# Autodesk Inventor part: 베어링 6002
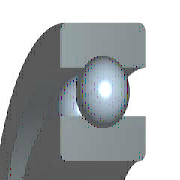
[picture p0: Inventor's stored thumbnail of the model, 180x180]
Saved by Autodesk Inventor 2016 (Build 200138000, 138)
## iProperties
IsCustomPart: 0
Created: 2012-02
Part Number: 베어링 6002
Material: 강철, 연강
Description: 깊은 그루브 볼 베어링
Document SubType Name: Modeling
Standard: KS B 2023
Designer: mduedu
Standards Organization: KS
Language: ko-KR
Size Designation: 6002 - 15 x 32 x 9
Categories: <MemberInstance><Categories><Category DisplayName="샤프트 부품" InternalName="7f7aeb1f-a693-4053-b835-cee3144e0d98" Mnemonic="SHFT"><Category DisplayName="베어링" Inter
Density: 1 g/cm^3
Appearance: 노란색
Author: mduedu
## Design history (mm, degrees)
sketch "스케치" dims "d0" = 4.42 (= -0.26 x WD + 0.26 x BD)
  geometry: L1 (2.29, 11.75)-(6.71, 11.75); L2 (4.5, 11.75)-(4.5, 9.54); L3 (4.5, 11.75)-(4.5, 13.96); L4 (2.858, 10.271)-(0, 10.271); L5 (0, 7.5)-(9, 7.5); L6 (2.858, 13.229)-(0, 13.229); L7 (0, 16)-(9, 16); L8 (9, 7.5)-(9, 10.271); L9 (6.142, 10.271)-(9, 10.271); L10 (6.142, 13.229)-(9, 13.229); L11 (9, 16)-(9, 13.229); L12 (-1.4, 0)-(8.4, 0) reference; L13 (0, -0.3)-(0, 5.3) reference
  constraints: 22 end point, 4 point on line, 2 collinear, 2 perpendicular, 2 symmetric about line, 1 midpoint, 1 parallel, 14 other
  dimensions: "d9" = 15 diameter of L5 L12 (= WD); "d11" = 32 diameter of L7 L12 (= BD); "d12" = 9 distance between parallel lines of L8 L13 (= KB); "d13" = 20.542 diameter of L9 L12 (= 0.326 x BD + 0.674 x WD)
revolve "본체" stored, may be unused: angle "d6" = 90 deg
revolve "볼" stored, may be unused: angle "d7" = 90 deg
pattern_circular "IDS_ARRAYBALL[SIMPL:T]" dims angle "d3" = 360 deg
body "Solid1"
fillet "모깎기1" dims "d1" = 0.3 (= KRS)
other parameters: "WD" = 15 [user parameter; used in 5 equation terms], "BD" = 32 [user parameter; used in 5 equation terms], "KB" = 9 [user parameter; used in 1 equation term], "KRS" = 0.3 [user parameter; used in 1 equation term], "d4" = 0, "d5" = 0, "d8" = 0, "d14" = 0, "d15" = 0, "BBA" = 0 [user parameter], "BC0" = 2850000 [user parameter], "BC" = 5590000 [user parameter], "BR" = 16 (= 0.5 x BD) [user parameter], "WR" = 7.5 (= 0.5 x WD) [user parameter]
